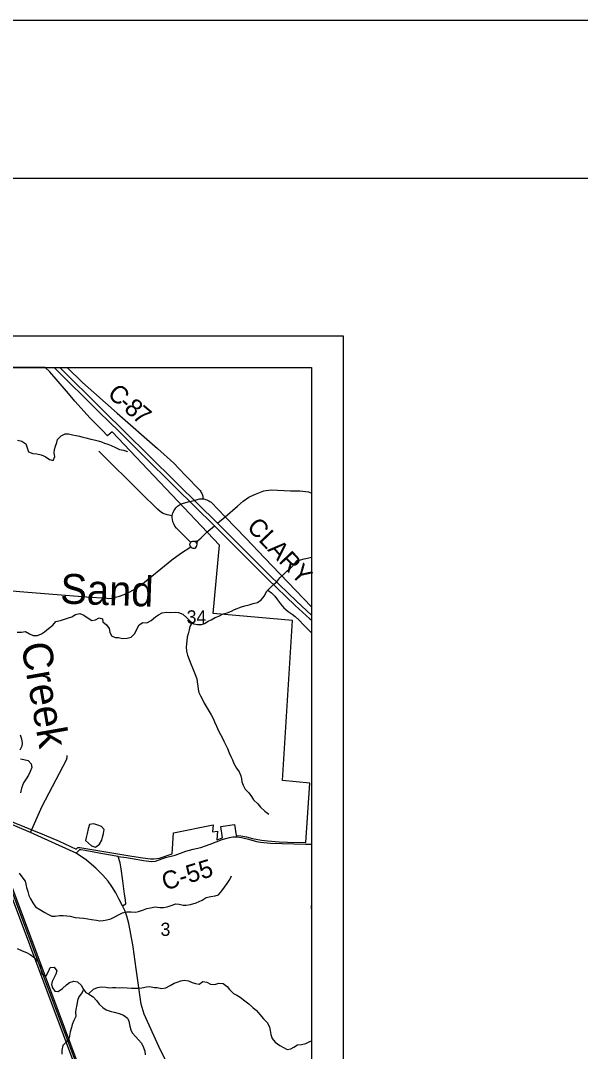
# Model space of a CAD drawing. Extents: x 0 to 34, y 0 to 22.
# Drawn here: x 7.976 to 9.754, y 18.731 to 22 of the extents above; entities that cross this region are included whole.
import ezdxf

# ---------------------------------------------------------------- set-up
doc = ezdxf.new("R2010")
doc.units = 0
for name, color, linetype in [('GM_X_City_Street', 7, 'Continuous'), ('GM_X_Corporation', 7, 'Continuous'), ('GM_X_County_Road', 7, 'Continuous'), ('GM_X_County_Road_Text', 7, 'Continuous'), ('GM_X_Major_River', 7, 'Continuous'), ('GM_X_Major_River_Text', 7, 'Continuous'), ('GM_X_Minor_Lake', 7, 'Continuous'), ('GM_X_Minor_River', 7, 'Continuous'), ('GM_X_Minor_River_Text', 7, 'Continuous'), ('GM_X_Rail_Line', 7, 'Continuous'), ('GM_X_Section_Text', 7, 'Continuous'), ('GM_X_State_Route', 7, 'Continuous'), ('GM_X_Township_Road', 7, 'Continuous'), ('GM_X_US_Route', 7, 'Continuous'), ('SH_Border', 7, 'Continuous'), ('SH_Cut_Line', 7, 'Continuous'), ('SH_Data', 7, 'Continuous')]:
    doc.layers.add(name, color=color, linetype=linetype)

msp = doc.modelspace()

# ---------------------------------------------------------------- linework, layer by layer
at = {"layer": 'GM_X_City_Street'}
for points in [[(8.458, 20.4294), (8.4473, 20.4309), (8.4414, 20.432), (8.435, 20.4342), (8.4286, 20.4363), (8.4235, 20.4396), (8.4192, 20.443), (8.4107, 20.4506), (8.359, 20.5011), (8.2247, 20.6344)], [(8.5369, 20.3393), (8.5356, 20.342), (8.5342, 20.344), (8.5329, 20.3457), (8.5287, 20.3474), (8.5261, 20.3482), (8.5217, 20.3477), (8.5184, 20.3467), (8.5165, 20.3447), (8.4717, 20.3903), (8.4659, 20.3967), (8.4625, 20.4034), (8.46, 20.4104), (8.4582, 20.4182), (8.4578, 20.4228), (8.458, 20.4294)], [(8.5164, 20.3311), (8.5149, 20.334), (8.5141, 20.337), (8.5141, 20.3395), (8.5152, 20.3422), (8.5165, 20.3447)], [(8.5164, 20.3311), (8.5196, 20.3278), (8.5229, 20.3265), (8.526, 20.3265), (8.5296, 20.3272), (8.5328, 20.3287), (8.5351, 20.3315), (8.5364, 20.3352), (8.5369, 20.3393)], [(7.5486, 20.221), (7.6513, 20.215), (7.7633, 20.2061), (7.8743, 20.1973), (7.9869, 20.1886), (8.0786, 20.1811), (8.1861, 20.1725), (8.2502, 20.1677), (8.257, 20.1674), (8.2667, 20.1684), (8.2777, 20.1709), (8.2899, 20.1745), (8.3049, 20.18), (8.3207, 20.1872), (8.3351, 20.1944), (8.3579, 20.209), (8.4567, 20.2898), (8.4843, 20.3102), (8.5164, 20.3311)]]:
    msp.add_lwpolyline(points, dxfattribs=at)
at = {"layer": 'GM_X_Corporation'}
for points in [[(8.1793, 18.6363), (7.8577, 19.4956), (8.0515, 19.417), (8.0993, 19.3971), (8.1528, 19.3717), (8.1584, 19.3773), (8.165, 19.3778), (8.3296, 19.3498), (8.3643, 19.3446), (8.3891, 19.3415), (8.3995, 19.341), (8.4173, 19.3434), (8.4571, 19.3568), (8.4623, 19.4241), (8.5873, 19.4492), (8.5859, 19.4265), (8.6012, 19.4296), (8.5997, 19.4018), (8.6175, 19.4084), (8.6126, 19.4439), (8.6557, 19.45), (8.6605, 19.4158), (8.6755, 19.4145), (8.6938, 19.4107), (8.713, 19.4062), (8.7407, 19.4004), (8.7607, 19.3982), (8.7973, 19.3957), (8.8234, 19.3941), (8.8819, 19.3932), (8.8947, 19.5818), (8.8076, 19.5902), (8.8392, 20.0976), (8.5877, 20.1199), (8.6074, 20.3366), (8.2672, 20.6952), (8.2528, 20.6833), (8.2359, 20.701), (8.197, 20.7393), (8.1488, 20.7927), (8.1285, 20.817), (8.0694, 20.8858), (8.0548, 20.9), (7.6183, 20.9)], [(7.8422, 19.5022), (8.1668, 18.6372)]]:
    msp.add_lwpolyline(points, dxfattribs=at)
at = {"layer": 'GM_X_County_Road'}
msp.add_line((8.8808, 19.388), (8.9, 19.3874), dxfattribs=at)
for points in [[(8.1244, 20.9), (8.1733, 20.8522), (8.2084, 20.8205), (8.2829, 20.7553), (8.4111, 20.6433), (8.4626, 20.5964), (8.4989, 20.5587)], [(8.4989, 20.5587), (8.5462, 20.5093), (8.5484, 20.506), (8.55, 20.5032), (8.5514, 20.5005), (8.5526, 20.4979), (8.554, 20.4945), (8.5548, 20.4917), (8.5554, 20.4873), (8.5549, 20.483)], [(8.7015, 20.4886), (8.7048, 20.4908), (8.7224, 20.4982), (8.7483, 20.5084), (8.7715, 20.5121), (8.8335, 20.5084), (8.8629, 20.5086), (8.89, 20.5056), (8.9, 20.5007)], [(8.4844, 20.466), (8.4866, 20.4671), (8.513, 20.4749), (8.5275, 20.4784), (8.5334, 20.4799)], [(8.5334, 20.4799), (8.5451, 20.4829), (8.5489, 20.4832), (8.5549, 20.483)], [(8.5549, 20.483), (8.5577, 20.4828), (8.5639, 20.4816), (8.5677, 20.4802), (8.5736, 20.4771), (8.5771, 20.475), (8.5812, 20.473), (8.626, 20.4264)], [(8.6014, 20.4057), (8.626, 20.4264), (8.665, 20.4602), (8.6826, 20.4758), (8.7015, 20.4886)], [(8.458, 20.4294), (8.4591, 20.4355), (8.4609, 20.4403), (8.4627, 20.4451), (8.4657, 20.4497), (8.4695, 20.4546), (8.4746, 20.4599), (8.4807, 20.4641), (8.4844, 20.466)], [(8.626, 20.4264), (8.6921, 20.3576), (8.7504, 20.2965), (8.9, 20.1411)], [(8.5369, 20.3393), (8.5369, 20.3428), (8.5375, 20.3464), (8.5389, 20.3499), (8.5421, 20.3536), (8.5495, 20.3599), (8.5673, 20.3771)], [(8.5673, 20.3771), (8.568, 20.3778), (8.5917, 20.3974)], [(8.5389, 20.3499), (8.5359, 20.3487), (8.5334, 20.3481), (8.5287, 20.3474)], [(8.2864, 19.3483), (8.3121, 19.3455), (8.3668, 19.3361), (8.3916, 19.3327), (8.4042, 19.3344), (8.4369, 19.3454), (8.4676, 19.3532), (8.5015, 19.3654), (8.5238, 19.3719), (8.5484, 19.3774), (8.5778, 19.3874), (8.6163, 19.4023), (8.6399, 19.4094), (8.6505, 19.411), (8.6644, 19.4107), (8.6774, 19.4091), (8.7, 19.4033), (8.7249, 19.396), (8.738, 19.3939), (8.7699, 19.3915), (8.8808, 19.388)], [(8.2864, 19.3483), (8.2307, 19.3581), (8.1813, 19.3681), (8.1673, 19.37), (8.1639, 19.3694), (8.1525, 19.3591)], [(8.2997, 19.1927), (8.3101, 19.1986), (8.3092, 19.2117), (8.3063, 19.2295), (8.301, 19.2716), (8.2957, 19.3092), (8.2929, 19.3282), (8.2864, 19.3483)]]:
    msp.add_lwpolyline(points, dxfattribs=at)
at = {"layer": 'GM_X_Major_River'}
for points in [[(7.9755, 19.7349), (7.9788, 19.7223), (7.9813, 19.7082), (7.9805, 19.6988), (7.9739, 19.6859)], [(7.9756, 19.659), (7.987, 19.6566), (8.0009, 19.6534), (8.0103, 19.6424), (8.0117, 19.631), (8.0071, 19.6181), (8.0013, 19.6068), (7.994, 19.5947), (7.9859, 19.5819), (7.979, 19.5656), (7.9762, 19.5508)], [(7.9652, 19.0569), (7.9811, 19.0495), (7.9947, 19.0445), (8.0064, 19.0383), (8.0184, 19.0295), (8.0316, 19.0154), (8.0368, 19.0055), (8.0398, 18.996), (8.0419, 18.9857), (8.0453, 18.9758), (8.0581, 18.97), (8.065, 18.9836), (8.0708, 18.9965), (8.0826, 18.9975), (8.0916, 18.9865), (8.0888, 18.9751), (8.0827, 18.9649), (8.0765, 18.9528), (8.0742, 18.943), (8.0782, 18.9319), (8.0854, 18.9216), (8.0956, 18.9208), (8.1093, 18.9302), (8.1223, 18.9418), (8.1322, 18.9486), (8.1451, 18.953), (8.1576, 18.951), (8.17, 18.9399), (8.1741, 18.93), (8.1839, 18.9174), (8.1952, 18.9113), (8.2065, 18.9032), (8.2178, 18.8925), (8.2256, 18.8807), (8.2373, 18.8696), (8.2478, 18.8627), (8.2637, 18.8572), (8.2735, 18.8545), (8.289, 18.8506), (8.303, 18.8459), (8.3162, 18.8356), (8.3203, 18.826), (8.3228, 18.8105), (8.3265, 18.7994), (8.331, 18.7899), (8.3422, 18.7765), (8.3509, 18.767), (8.3599, 18.7567), (8.3662, 18.7433), (8.371, 18.7312), (8.3721, 18.7198)]]:
    msp.add_lwpolyline(points, dxfattribs=at)
at = {"layer": 'GM_X_Minor_Lake'}
for points in [[(8.2126, 19.4508), (8.2083, 19.452), (8.1951, 19.4501), (8.1909, 19.4368), (8.1878, 19.4213), (8.1843, 19.4088), (8.1824, 19.3993)], [(8.1824, 19.3993), (8.202, 19.383), (8.2137, 19.378), (8.227, 19.3882), (8.2346, 19.4003), (8.2366, 19.4098), (8.2396, 19.4219), (8.2416, 19.434), (8.2337, 19.4439), (8.2212, 19.4485), (8.2126, 19.4508)], [(8.9, 19.1934), (8.8993, 19.1929), (8.8985, 19.183), (8.9, 19.1826)]]:
    msp.add_lwpolyline(points, dxfattribs=at)
at = {"layer": 'GM_X_Minor_River'}
for points in [[(7.9669, 20.669), (7.9801, 20.6659), (7.9926, 20.6579), (7.9971, 20.6446), (8.0019, 20.632), (8.0152, 20.6267), (8.028, 20.6255), (8.0417, 20.6228), (8.0541, 20.6178), (8.0681, 20.6076), (8.0798, 20.6045), (8.0852, 20.617), (8.0833, 20.6291), (8.0841, 20.6397), (8.0872, 20.65), (8.091, 20.6621), (8.0937, 20.6716), (8.1047, 20.6825), (8.1176, 20.6893), (8.1282, 20.6893), (8.141, 20.6866), (8.1528, 20.6839), (8.163, 20.6816), (8.1739, 20.6785), (8.1838, 20.6762), (8.1996, 20.6727), (8.2099, 20.6704), (8.2227, 20.6669), (8.2329, 20.6643), (8.2427, 20.6601), (8.253, 20.657), (8.2643, 20.6528), (8.2775, 20.6463), (8.29, 20.6402), (8.3028, 20.6371), (8.3153, 20.6329)], [(7.9652, 20.0607), (7.9788, 20.0606), (7.992, 20.0621), (8.0045, 20.0552), (8.0166, 20.0499), (8.0299, 20.0502), (8.0431, 20.0551), (8.0526, 20.0615), (8.0651, 20.0717), (8.0784, 20.0827), (8.0887, 20.094), (8.1027, 20.097), (8.1159, 20.1011), (8.1281, 20.1053), (8.1387, 20.109), (8.1512, 20.1162), (8.1641, 20.1199), (8.1777, 20.1138), (8.1875, 20.1066), (8.2022, 20.0978), (8.2139, 20.0989), (8.2257, 20.1061), (8.2363, 20.103), (8.2378, 20.0935), (8.2487, 20.0836), (8.2578, 20.0722), (8.2596, 20.0604), (8.2645, 20.0491), (8.2766, 20.0433), (8.2868, 20.0433), (8.3, 20.0406), (8.3148, 20.0413), (8.3277, 20.0443), (8.3391, 20.0564), (8.3452, 20.0696), (8.3532, 20.0833), (8.3649, 20.0908), (8.377, 20.09), (8.3914, 20.0968), (8.4047, 20.1093), (8.4142, 20.1153), (8.426, 20.1213), (8.4396, 20.1239), (8.4528, 20.1231), (8.468, 20.1238), (8.4782, 20.1223), (8.4914, 20.1177), (8.5043, 20.1059), (8.5163, 20.0945), (8.5265, 20.0869), (8.5375, 20.0842), (8.5507, 20.0841), (8.5606, 20.0879), (8.5716, 20.095), (8.5811, 20.0992), (8.5943, 20.1063), (8.6053, 20.1112), (8.6197, 20.118), (8.6318, 20.1221), (8.6455, 20.1274), (8.6553, 20.1319), (8.6781, 20.1409), (8.6883, 20.1439), (8.7023, 20.1473), (8.7144, 20.1507), (8.7281, 20.154), (8.7406, 20.1624), (8.7509, 20.176), (8.7566, 20.1888), (8.7687, 20.2009), (8.7805, 20.2127), (8.79, 20.2202), (8.7999, 20.2331), (8.8128, 20.2452), (8.8227, 20.255), (8.8322, 20.2622), (8.8424, 20.2731), (8.8549, 20.2871), (8.8652, 20.2901), (8.8769, 20.2927), (8.8868, 20.295), (8.8996, 20.298), (8.9, 20.2981)], [(8.7613, 20.1936), (8.7725, 20.1846), (8.7838, 20.1743), (8.7925, 20.1633), (8.8011, 20.1504), (8.812, 20.1375), (8.826, 20.126), (8.8381, 20.1169), (8.8479, 20.11), (8.8604, 20.0982), (8.8736, 20.0849), (8.886, 20.072), (8.8973, 20.0606), (8.9, 20.0586)], [(8.5209, 20.091), (8.5132, 20.0782), (8.5117, 20.0679), (8.5086, 20.0547), (8.5056, 20.0444), (8.504, 20.0327), (8.5032, 20.0228), (8.5024, 20.0126), (8.5028, 20.0001), (8.5065, 19.9872), (8.5114, 19.9735), (8.5166, 19.9595), (8.5223, 19.9469), (8.5264, 19.9367), (8.5305, 19.9257), (8.5354, 19.912), (8.5372, 19.9025), (8.5387, 19.8889), (8.5398, 19.879), (8.542, 19.8691), (8.5477, 19.8581), (8.5537, 19.8467), (8.5593, 19.8353), (8.5654, 19.8243), (8.5748, 19.8091), (8.5819, 19.7981), (8.5876, 19.7867), (8.5924, 19.776), (8.5981, 19.7624), (8.6052, 19.7476), (8.6112, 19.7362), (8.6165, 19.7259), (8.6217, 19.7149), (8.6281, 19.7016), (8.6334, 19.6913), (8.6386, 19.6773), (8.6435, 19.6655), (8.6488, 19.6549), (8.6537, 19.6442), (8.6623, 19.6294), (8.6699, 19.6173), (8.6751, 19.6051), (8.6774, 19.5956), (8.6792, 19.5854), (8.6826, 19.5755), (8.689, 19.5622), (8.701, 19.5504), (8.7097, 19.5386), (8.7161, 19.5284), (8.7293, 19.5154), (8.7384, 19.5055), (8.7519, 19.493), (8.7648, 19.4834)], [(7.972, 19.2958), (7.9803, 19.284), (7.9905, 19.2707), (7.9931, 19.2608), (7.9957, 19.2509), (7.9991, 19.2376), (8.0024, 19.2251), (8.0081, 19.2145), (8.0156, 19.2019), (8.0239, 19.1886), (8.0371, 19.1803), (8.053, 19.1707), (8.0632, 19.1658), (8.0752, 19.1596), (8.0866, 19.1592), (8.0995, 19.1615), (8.1112, 19.1618), (8.1229, 19.1606), (8.1339, 19.1591), (8.1498, 19.1552), (8.163, 19.1537), (8.1766, 19.1536), (8.1899, 19.1513), (8.202, 19.149), (8.2171, 19.1466), (8.2273, 19.1443), (8.2383, 19.1454), (8.2501, 19.1484), (8.2633, 19.1514), (8.2781, 19.1586), (8.2876, 19.1642), (8.2997, 19.1703), (8.3133, 19.1732), (8.3277, 19.1736), (8.3413, 19.172), (8.3512, 19.1743), (8.3671, 19.1791), (8.3777, 19.1836), (8.3887, 19.1855), (8.4038, 19.1892), (8.4186, 19.1873), (8.43, 19.1873), (8.4421, 19.1887), (8.4546, 19.1936), (8.4694, 19.1981), (8.4799, 19.1977), (8.4924, 19.1943), (8.5023, 19.1946), (8.5155, 19.1968), (8.5341, 19.2013), (8.5436, 19.2055), (8.553, 19.21), (8.5659, 19.2187), (8.5807, 19.222), (8.5936, 19.2239), (8.6046, 19.2273), (8.6148, 19.2394), (8.6239, 19.2518), (8.6319, 19.2628), (8.6403, 19.2761), (8.6456, 19.2878)], [(8.1917, 18.9131), (8.208, 18.9279), (8.2206, 18.9331), (8.2334, 18.935), (8.2474, 18.9338), (8.2576, 18.9326), (8.2686, 18.9333), (8.2785, 18.9333), (8.2906, 18.9325), (8.3015, 18.9329), (8.3144, 18.9324), (8.328, 18.9312), (8.3519, 18.9312), (8.3617, 18.9319), (8.3761, 18.9349), (8.3867, 18.936), (8.4007, 18.9333), (8.4105, 18.9336), (8.4234, 18.9305), (8.437, 18.932), (8.4511, 18.9399), (8.4636, 18.9467), (8.473, 18.9501), (8.4855, 18.9542), (8.4961, 18.9565), (8.5094, 18.9545), (8.5211, 18.9496), (8.5313, 18.9457), (8.5434, 18.9434), (8.5552, 18.9521), (8.5677, 18.9502), (8.5794, 18.9437), (8.593, 18.9429), (8.6059, 18.947), (8.6195, 18.9462), (8.6323, 18.9367), (8.6391, 18.9264), (8.6523, 18.9142), (8.6625, 18.9093), (8.6731, 18.9028), (8.6878, 18.891), (8.7014, 18.8814), (8.7142, 18.8693), (8.7248, 18.8601), (8.7361, 18.8472), (8.7478, 18.8339), (8.7606, 18.8213), (8.767, 18.8073), (8.7692, 18.797), (8.7711, 18.7841), (8.7748, 18.7716), (8.785, 18.7602), (8.7993, 18.7488), (8.8107, 18.743), (8.8231, 18.7369), (8.8341, 18.7384), (8.844, 18.7444), (8.8557, 18.7512), (8.8686, 18.7527), (8.8815, 18.7553), (8.8921, 18.7606), (8.9, 18.7643)], [(8.1765, 18.927), (8.1721, 18.9174), (8.1614, 18.9041), (8.1572, 18.8916), (8.1549, 18.8787), (8.1514, 18.864), (8.151, 18.8545), (8.1514, 18.8408), (8.1456, 18.8287), (8.1403, 18.8162), (8.1376, 18.8064), (8.1334, 18.7923), (8.1318, 18.7798), (8.1299, 18.7704), (8.1212, 18.7602), (8.1102, 18.7488), (8.1075, 18.7348), (8.1078, 18.7223)]]:
    msp.add_lwpolyline(points, dxfattribs=at)
at = {"layer": 'GM_X_Rail_Line'}
msp.add_lwpolyline([(8.1892, 18.5986), (8.0513, 18.9649), (7.8912, 19.3911), (7.7899, 19.661)], dxfattribs=at)
at = {"layer": 'GM_X_State_Route'}
for points in [[(8.0984, 19.3837), (8.0083, 19.4248), (7.966, 19.443), (7.8065, 19.5105), (7.6304, 19.5849), (7.6259, 19.587)], [(8.1853, 19.337), (8.1525, 19.3591), (8.0984, 19.3837)], [(8.2291, 19.2983), (8.2158, 19.3118), (8.187, 19.3358), (8.1853, 19.337)], [(8.3199, 19.1362), (8.3133, 19.1591), (8.3076, 19.1771), (8.2997, 19.1927), (8.289, 19.2123), (8.2784, 19.2334), (8.2657, 19.2535), (8.254, 19.271), (8.2375, 19.2898), (8.2291, 19.2983)], [(8.4685, 18.6396), (8.4149, 18.7463), (8.3688, 18.8488), (8.3595, 18.8809), (8.3437, 18.9927), (8.3335, 19.0623), (8.3243, 19.1142), (8.3199, 19.1362)]]:
    msp.add_lwpolyline(points, dxfattribs=at)
at = {"layer": 'GM_X_Township_Road'}
msp.add_lwpolyline([(8.0083, 19.4248), (8.0453, 19.5083), (8.122, 19.6554), (8.1243, 19.6623), (8.1247, 19.6693)], dxfattribs=at)
at = {"layer": 'GM_X_US_Route'}
for points in [[(8.0825, 20.9), (8.2261, 20.7586), (8.2894, 20.6966), (8.3373, 20.6487)], [(8.1006, 20.9), (8.2329, 20.769), (8.3134, 20.6891), (8.378, 20.6256), (8.4751, 20.53), (8.6014, 20.4057)], [(8.3373, 20.6487), (8.3626, 20.6234), (8.4674, 20.5198), (8.5917, 20.3974)], [(8.6014, 20.4057), (8.6793, 20.3282), (8.7681, 20.2398), (8.8533, 20.1572), (8.9, 20.1142)], [(8.5917, 20.3974), (8.6711, 20.3183), (8.7598, 20.2299), (8.8482, 20.1446), (8.895, 20.1028), (8.9, 20.0984)]]:
    msp.add_lwpolyline(points, dxfattribs=at)
at = {"layer": 'SH_Border'}
msp.add_lwpolyline([(1.5, 21.5), (33.5, 21.5), (33.5, 0.5), (1.5, 0.5)], close=True, dxfattribs=at)
at = {"layer": 'SH_Cut_Line'}
msp.add_lwpolyline([(0, 0), (34, 0), (34, 22), (0, 22)], close=True, dxfattribs=at)
at = {"layer": 'SH_Data'}
for p, q in [((2, 21), (9, 21)), ((9, 21), (9, 14)), ((2.1, 20.9), (8.9, 20.9)), ((8.9, 20.9), (8.9, 14.1))]:
    msp.add_line(p, q, dxfattribs=at)

# ---------------------------------------------------------------- texts
at = {"layer": 'GM_X_County_Road_Text'}
for s, height, rotation, p in [('C', 0.0568, 317.823, (8.2491, 20.8117)), ('-', 0.0568, 318.5269, (8.284, 20.78)), ('8', 0.0568, 319.126, (8.3018, 20.7643)), ('7', 0.0568, 319.5366, (8.3284, 20.7413)), ('CLARY', 0.05682, 313.4367, (8.6917, 20.3913)), ('C-55', 0.05682, 16.6987, (8.4344, 19.2405))]:
    msp.add_text(s, height=height, rotation=rotation, dxfattribs=at).set_placement(p)
at = {"layer": 'GM_X_Major_River_Text'}
msp.add_text('Creek', height=0.09471, rotation=279.999, dxfattribs=at).set_placement((7.9777, 20.021))
at = {"layer": 'GM_X_Minor_River_Text'}
msp.add_text('Sand', height=0.0947, rotation=357.9973, dxfattribs=at).set_placement((8.1013, 20.1514))
at = {"layer": 'GM_X_Section_Text'}
for s, height, p in [('34', 0.04186, (8.5036, 20.0878)), ('3', 0.0419, (8.4207, 19.097))]:
    msp.add_text(s, height=height, rotation=0, dxfattribs=at).set_placement(p)

doc.saveas('drawing.dxf')
